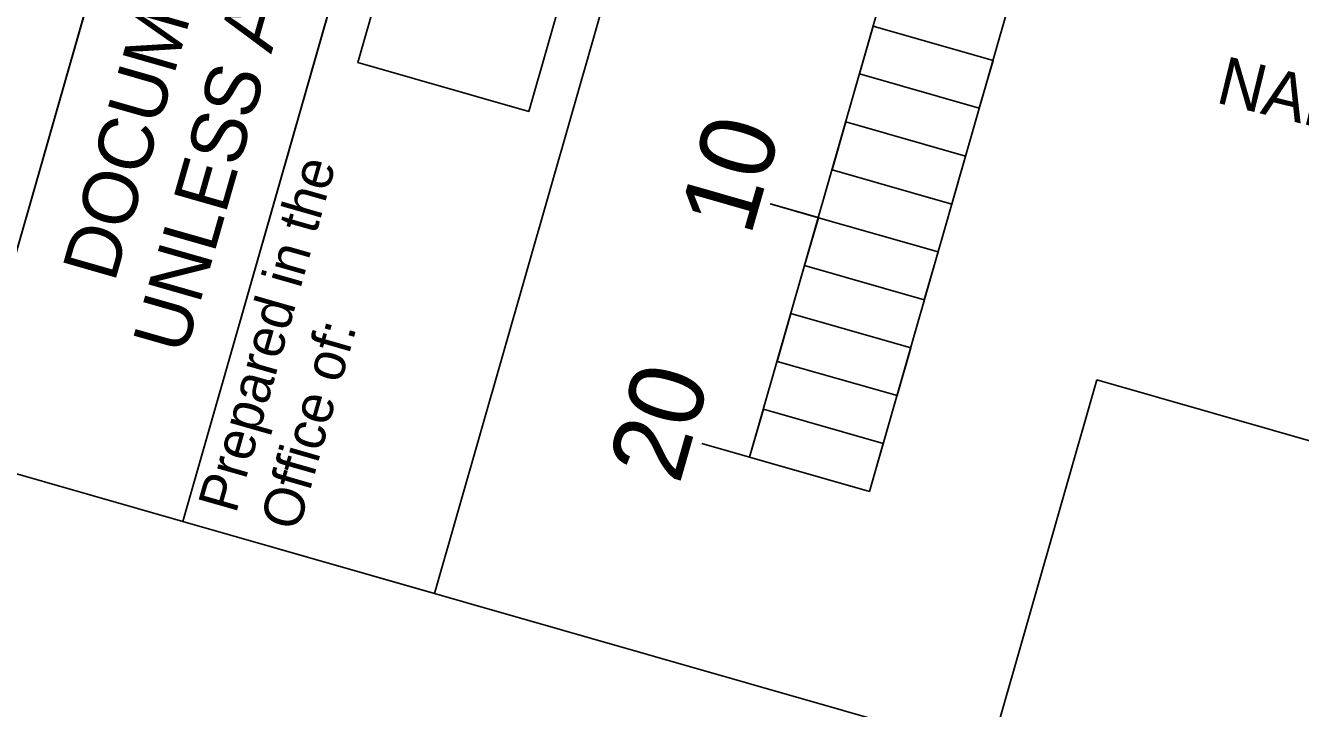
# Model space of a CAD drawing. Extents: x 2097440 to 2098186, y 685688 to 689676.
# Drawn here: x 2097803.9 to 2097855.1, y 689488.2 to 689515.6 of the extents above; entities that cross this region are included whole.
import ezdxf

# ---------------------------------------------------------------- set-up
doc = ezdxf.new("R2010")
doc.units = 0
for name, color, linetype in [('Default', 7, 'Continuous'), ('Sheet Block Title CELL', 7, 'Continuous'), ('Sheet Data Field CELL', 7, 'Continuous'), ('Sheet Layout Plan Border', 7, 'Continuous'), ('Sheet Profile CELL', 7, 'Continuous'), ('Sheet Sticker Exception Certification CELL', 7, 'Continuous'), ('Sheet Title CELL', 7, 'Continuous')]:
    doc.layers.add(name, color=color, linetype=linetype)

msp = doc.modelspace()

# ---------------------------------------------------------------- linework, layer by layer
at = {"layer": 'Sheet Block Title CELL'}
for points in [[(2097810.237, 689495.698), (2097832.259, 689572.631), (2097842.356, 689569.741), (2097820.334, 689492.808)], [(2097817.26, 689514.118), (2097819.523, 689522.023), (2097826.384, 689520.059), (2097824.121, 689512.154)]]:
    msp.add_lwpolyline(points, close=True, dxfattribs=at)
msp.add_lwpolyline([(2097819.523, 689522.023), (2097817.26, 689514.118), (2097824.121, 689512.154), (2097826.384, 689520.059), (2097819.523, 689522.023)], dxfattribs=at)
at = {"layer": 'Sheet Data Field CELL'}
for p, q in [((2097835.739, 689507.894), (2097833.816, 689508.444)), ((2097832.982, 689498.281), (2097831.064, 689498.83))]:
    msp.add_line(p, q, dxfattribs=at)
at = {"layer": 'Sheet Layout Plan Border'}
msp.add_lwpolyline([(2097605.204, 689013.525), (2098008.986, 688897.94), (2098157.348, 689412.514), (2097846.919, 689501.376), (2097842.639, 689486.423), (2097810.237, 689495.698), (2097801.2, 689498.285), (2097757.937, 689510.669), (2097753.13, 689512.045), (2097748.304, 689513.427)], close=True, dxfattribs=at)
at = {"layer": 'Sheet Profile CELL'}
msp.add_lwpolyline([(2097757.937, 689510.669), (2097768.951, 689549.144), (2097812.213, 689536.76), (2097801.2, 689498.285)], close=True, dxfattribs=at)
at = {"layer": 'Sheet Sticker Exception Certification CELL'}
for p, q in [((2097801.2, 689498.285), (2097823.22, 689575.21)), ((2097832.257, 689572.623), (2097810.237, 689495.698)), ((2097810.237, 689495.698), (2097801.2, 689498.285))]:
    msp.add_line(p, q, dxfattribs=at)
at = {"layer": 'Sheet Title CELL'}
for p, q in [((2097849.498, 689555.959), (2097832.986, 689498.275)), ((2097837.793, 689496.899), (2097854.31, 689554.581)), ((2097836.839, 689511.735), (2097841.646, 689510.359)), ((2097835.743, 689507.888), (2097833.815, 689508.439)), ((2097832.986, 689498.275), (2097831.068, 689498.824)), ((2097831.068, 689498.824), (2097831.068, 689498.824)), ((2097832.986, 689498.275), (2097837.793, 689496.899)), ((2097832.986, 689498.275), (2097832.986, 689498.275))]:
    msp.add_line(p, q, dxfattribs=at)
for points in [[(2097837.389, 689513.657), (2097837.939, 689515.58), (2097842.751, 689514.203), (2097842.196, 689512.281)], [(2097836.293, 689509.81), (2097836.839, 689511.735), (2097841.646, 689510.359), (2097841.095, 689508.436)], [(2097835.192, 689505.965), (2097835.743, 689507.888), (2097840.545, 689506.513), (2097839.994, 689504.59)], [(2097834.087, 689502.121), (2097834.642, 689504.042), (2097839.449, 689502.666), (2097838.9, 689500.748)], [(2097832.986, 689498.275), (2097833.536, 689500.198), (2097838.343, 689498.822), (2097837.793, 689496.899)]]:
    msp.add_lwpolyline(points, close=True, dxfattribs=at)

# ---------------------------------------------------------------- texts
at = {"layer": 'Default'}
msp.add_text('NAD 83 NA 2011', height=1.92, rotation=346.2222, dxfattribs=at).set_placement((2097851.638, 689512.521))
at = {"layer": 'Sheet Block Title CELL'}
for s, height, p in [('Prepared in the ', 1.60046, (2097812.368, 689495.971)), ('Office of:', 1.6005, (2097814.868, 689495.255))]:
    msp.add_text(s, height=height, rotation=74.0259, dxfattribs=at).set_placement(p)
at = {"layer": 'Sheet Data Field CELL'}
for s, p in [('10', (2097833.015, 689507.099)), ('20', (2097830.164, 689497.14))]:
    msp.add_text(s, height=3, rotation=74.0259, dxfattribs=at).set_placement(p)
at = {"layer": 'Sheet Sticker Exception Certification CELL'}
for s, p in [('UNLESS ALL SIGNATURES COMPLETED', (2097810.323, 689502.33)), ('DOCUMENT NOT CONSIDERED FINAL', (2097807.498, 689505.249))]:
    msp.add_text(s, height=2.2, rotation=74.0259, dxfattribs=at).set_placement(p)

doc.saveas('drawing.dxf')
